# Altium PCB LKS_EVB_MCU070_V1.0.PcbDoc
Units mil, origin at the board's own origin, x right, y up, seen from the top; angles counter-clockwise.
Board outline 2625 x 1560 mil, 2 copper layers (Top Layer, Bottom Layer); 44 components, 81 nets, 209 pads, 64 vias.
Unrouted connection lines stored in the file: 4.
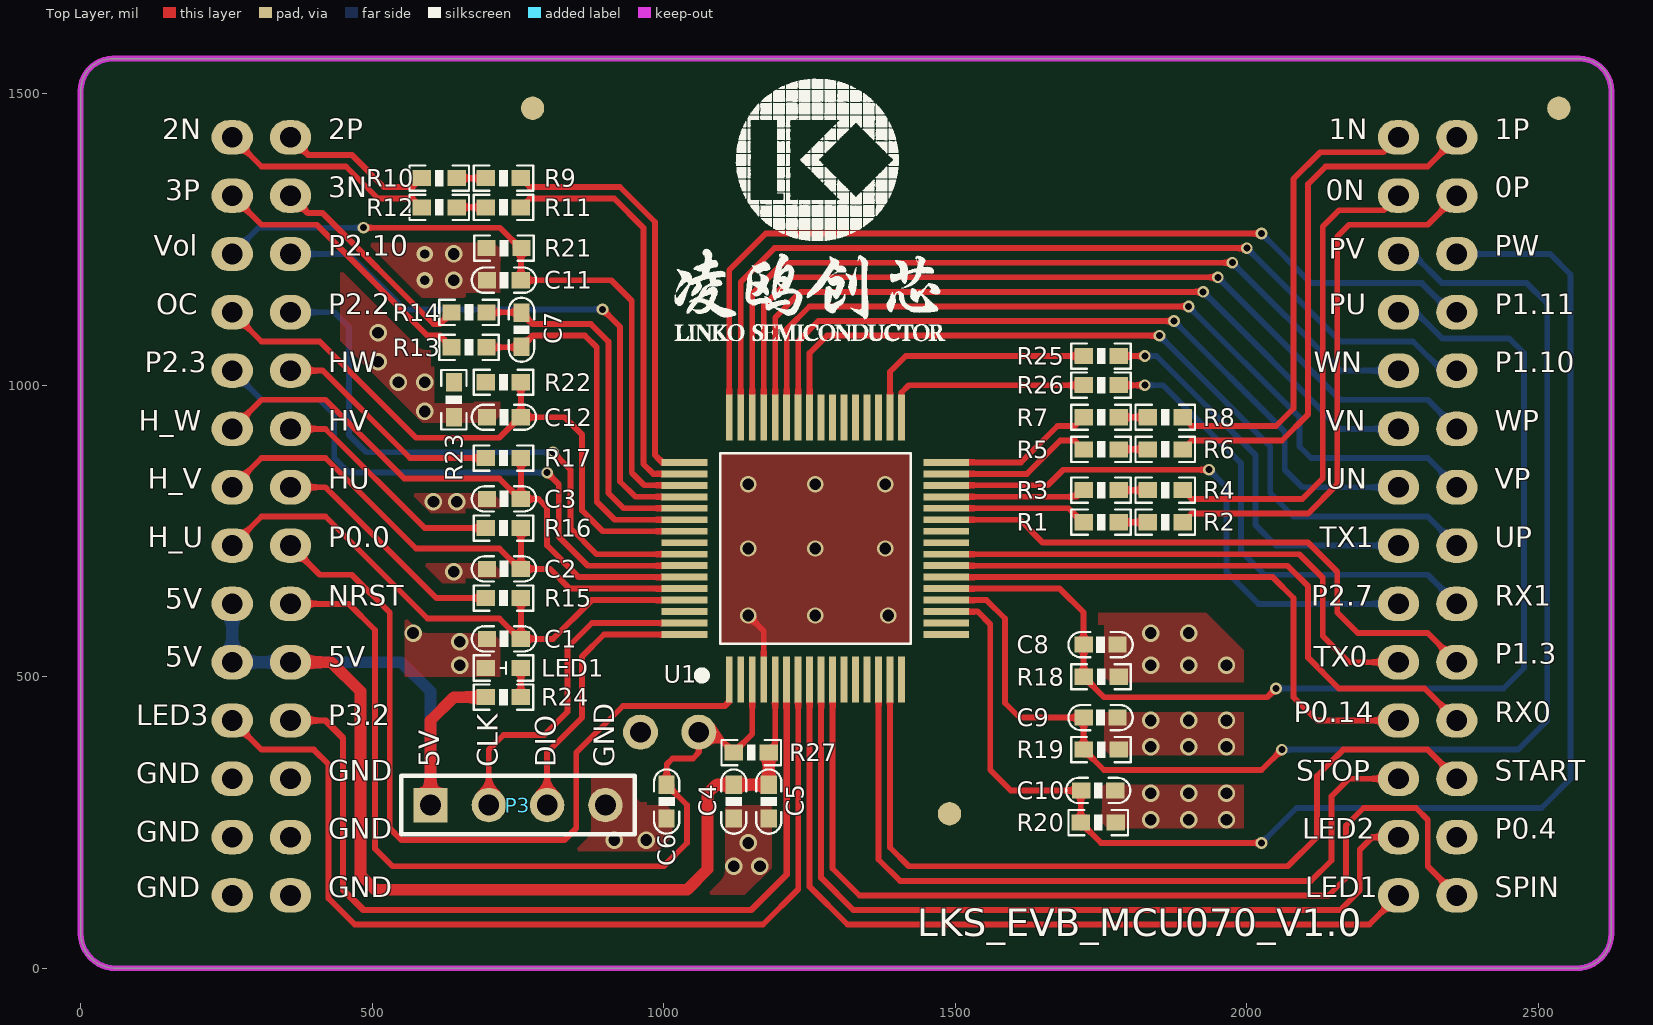
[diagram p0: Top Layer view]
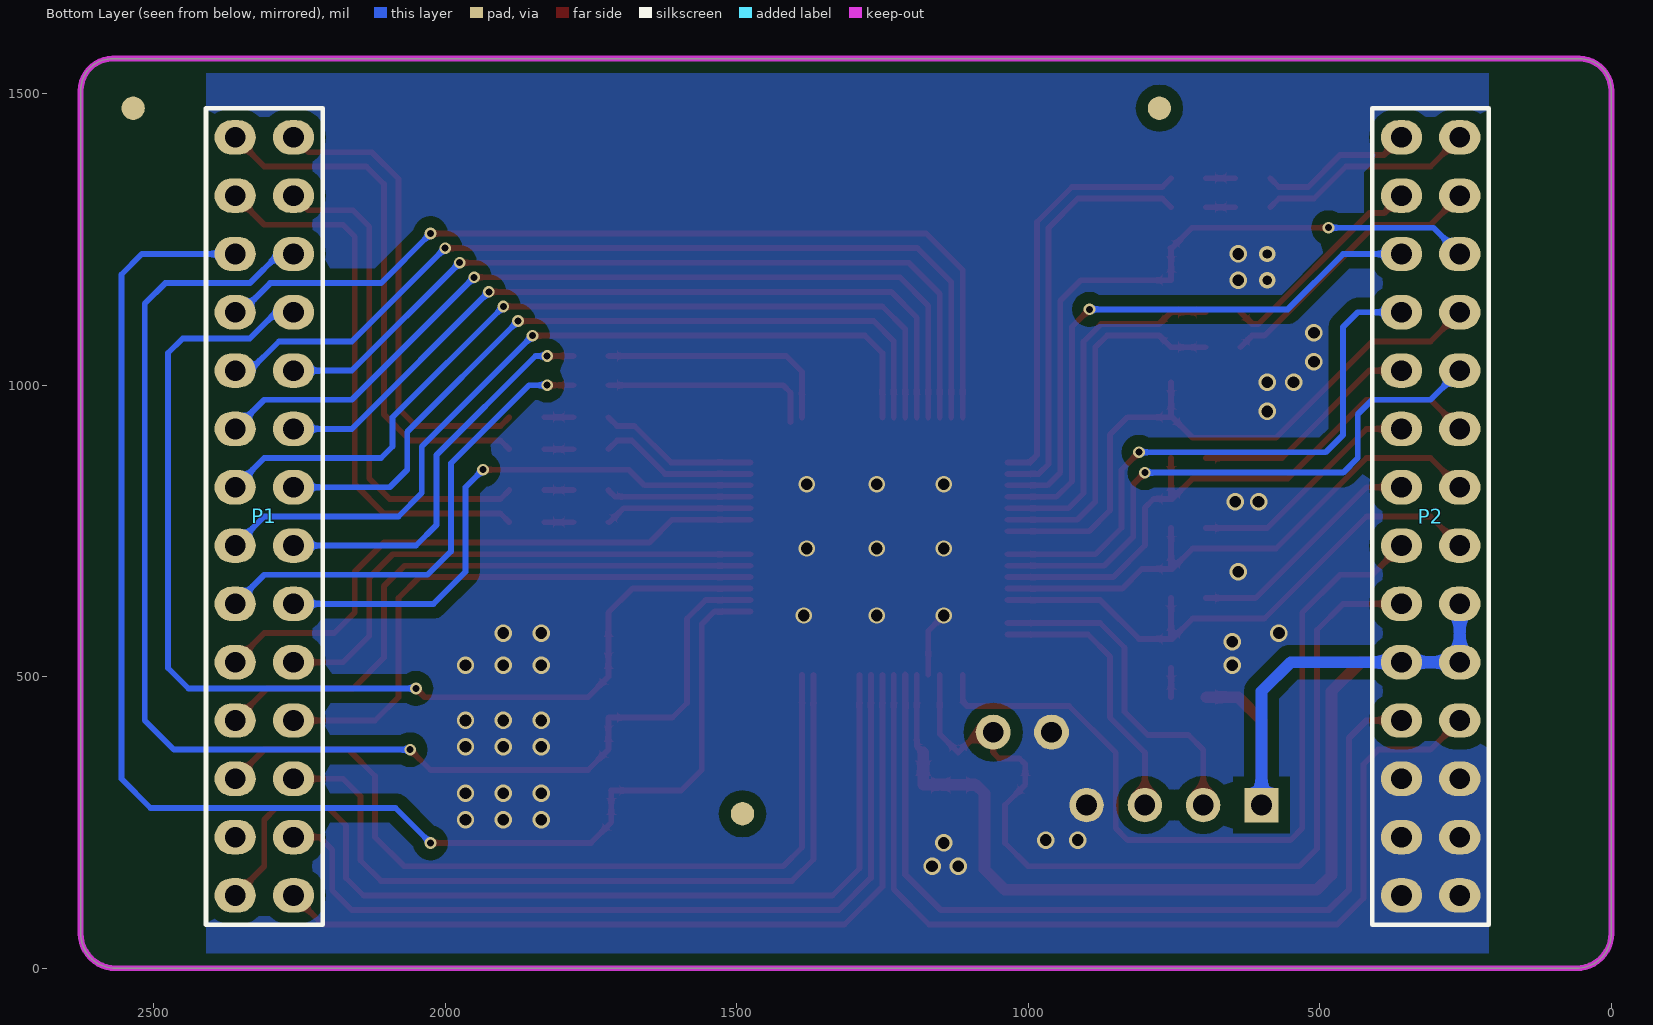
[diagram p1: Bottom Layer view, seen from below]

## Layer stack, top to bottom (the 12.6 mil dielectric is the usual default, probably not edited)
Top Solder: solder mask 0.4, Solder Resist, Dk 3.5
Top Layer: signal copper 1.4
Dielectric1: dielectric 12.6, FR-4, Dk 4.8
Bottom Layer: signal copper 1.4
Bottom Solder: solder mask 0.4, Solder Resist, Dk 3.5

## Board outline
0,60 0,1505 cw(c55,1505) 55,1560 2570,1560 cw(c2570,1505) 2625,1505 2625,60 cw(c2565,60) 2565,0 60,0 cw(c60,60)

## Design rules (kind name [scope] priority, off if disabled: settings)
Clearance Clearance_2 [InPolygon] p1: gap=20 ignorepadtopadclearanceinfootprint=FALSE except(0: Arc-Hole Track-Hole SMDPad-Hole THPad-Hole Via-Hole Fill-Hole Poly-Hole Region-Hole Text-Hole)
Clearance Clearance_1 [All] p2: gap=0 ignorepadtopadclearanceinfootprint=FALSE
ComponentClearance [All] p1: gap=0 collisioncheckmode=3 verticalgap=0 showdistances=FALSE
FabricationTestpoint [(IsPad And (OnTopLayer Or OnBottomLayer))] p1: side=3 testpointundercomponent=TRUE minsize=40 maxsize=100 preferedsize=60 minholesize=0 maxholesize=40 preferedholesize=32 testpointgrid=1 allowsidetop=TRUE allowsidebottom=TRUE usegrid=TRUE gridtolerance=0.01
HoleSize [All] p1: absolutevalues=TRUE maxlimit=100 minlimit=0 maxpercent=80.000 minpercent=20.000
PolygonConnect [All] p1: connectstyle=Direct reliefconductorwidth=10 reliefentries=4 polygonreliefangle="90 Angle" airgapwidth=10
RoutingVias [All] p1: holewidth=28 width=50 viastyle="Through Hole" minholewidth=0 minwidth=10 maxholewidth=28 maxwidth=50
SilkToSolderMaskClearance SilkscreenOverComponentPads [IsPad] p1: minsilkscreentomaskgap=10 clearancetoexposedcopper=TRUE
SolderMaskExpansion [All] p1: expansion=4 istentingtop=FALSE
Width [All] p1: maxlimit=100 minlimit=1 preferedwidth=10
26 further rules are at their usual default settings.

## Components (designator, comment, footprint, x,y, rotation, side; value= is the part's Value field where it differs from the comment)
C1 "10nF/16V" 0603C 726,565 r180 top
C2 "10nF/16V" 0603C 726,685 r180 top
C3 "10nF/16V" 0603C 726,805 r180 top
C4 "10uF/10V" 0603C 1120,285.95 r90 top
C5 "100nF/50V" 0603C 1180,285.95 r90 top
C6 "100nF/50V" 0603C 1005,286 r270 top
C7 "1nF/50V" 0603C 756,1095 r90 top
C8 "1nF/50V" 0603C 1749,555 r0 top
C9 "1nF/50V" 0603C 1749,430 r0 top
C10 "1nF/50V" 0603C 1745,305 r0 top
C11 "100nF/50V" 0603C 725.94,1180 r0 top
C12 "1nF/50V" 0603C 725.94,945 r0 top
LED1 "LED" "LED 0603R" 725,515 r180 top
P1 "Header 14X2A" "HDR 2X14 底层" 2260,1425 r180 bottom locked
P2 "Header 14X2A" "HDR 2X14 底层" 260,1425 r180 bottom locked
P3 "Header 4" HDR1X4 600,280 r0 top
R1 "20K1%" 0603R 1750,765 r180 top value=K
R2 "20K1%" 0603R 1860,765 r180 top value=K
R3 "20K1%" 0603R 1750,820 r180 top value=K
R4 "20K1%" 0603R 1860,820 r180 top value=K
R5 "20K1%" 0603R 1750,890 r180 top value=K
R6 "20K1%" 0603R 1860,890 r180 top value=K
R7 "20K1%" 0603R 1750,945 r180 top value=K
R8 "20K1%" 0603R 1860,945 r180 top value=K
R9 "20K1%" 0603R 725,1355 r0 top value=K
R10 "20K1%" 0603R 615,1355 r0 top value=K
R11 "20K1%" 0603R 725,1305 r0 top value=K
R12 "20K1%" 0603R 615,1305 r0 top value=K
R13 "1K1%" 0603R 666,1065 r0 top value=K
R14 "1K1%" 0603R 666,1125 r0 top value=K
R15 "2K" 0603R 725,635 r0 top value=K
R16 "2K" 0603R 725,755 r0 top value=K
R17 "2K" 0603R 725,875 r0 top value=K
R18 "1K" 0603R 1750,500 r0 top value=K
R19 "1K" 0603R 1750,375 r0 top value=K
R20 "1K" 0603R 1745,250 r0 top value=K
R21 "1K1%" 0603R 725.94,1235 r0 top value=K
R22 "1K1%" 0603R 725,1005 r180 top value=K
R23 "10R" 0603R 640,975 r270 top value=K
R24 "330R" 0603R 725,465 r0 top value=K
R25 "10R" 0603R 1750,1050 r0 top value=K
R26 "10R" 0603R 1750,1000 r0 top value=K
R27 "20K1%" 0603R 1150,370 r0 top value=K
U1 "LKS32MC070RBT8" LQFP64 1260,720 r0 top locked

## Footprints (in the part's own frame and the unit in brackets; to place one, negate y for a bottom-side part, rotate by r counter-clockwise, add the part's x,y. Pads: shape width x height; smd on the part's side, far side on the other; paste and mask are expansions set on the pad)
0603C [mm] "电容"
  rect 0.8x0.7 smd: 1(-0.737,0) 2(0.738,0)
  silkscreen extent -1.4,-0.55 1.4,0.55, body extent -0.8,-0.41 0.8,0.41, height 0.81
0603R [mm] "电阻"
  rect 0.8x0.7 smd: 1(-0.762,0) 2(0.762,0)
  silkscreen extent -1.3,-0.55 1.3,0.55, body extent -0.8,-0.4 0.8,0.4, height 0.45
HDR1X4 [mm] "Connector; Header; 4 Position"
  rect 1.5x1.5 hole 0.9: 1(0,0)
  round 1.5 hole 0.9: 2(2.54,0) 3(5.08,0) 4(7.62,0)
  silkscreen extent -1.27,-1.27 8.89,1.27
"HDR 2X14 底层" [mm] "双排针 2.54mm 底层"
  oval 1.8x1.5 hole 0.9: 1(0,0) 2(0,-2.54) 3(0,-5.08) 4(0,-7.62) 5(0,-10.16) 6(0,-12.7) 7(0,-15.24) 8(0,-17.78) 9(0,-20.32) 10(0,-22.86) 11(0,-25.4) 12(0,-27.94) 13(0,-30.48) 14(0,-33.02) 15(-2.54,0) 16(-2.54,-2.54) 17(-2.54,-5.08) 18(-2.54,-7.62) 19(-2.54,-10.16) 20(-2.54,-12.7) 21(-2.54,-15.24) 22(-2.54,-17.78) 23(-2.54,-20.32) 24(-2.54,-22.86) 25(-2.54,-25.4) 26(-2.54,-27.94) 27(-2.54,-30.48) 28(-2.54,-33.02)
  silkscreen extent -3.81,-34.29 1.27,1.27, body extent -3.81,-34.29 1.27,1.27, height 8.5
"LED 0603R" [mm] "LED"
  rect 0.8x0.7 smd: 1(-0.762,0) 2(0.762,0)
  silkscreen extent -1.3,-0.55 1.3,0.55, body extent -0.8,-0.4 0.8,0.4, height 0.47
LQFP64 [mm] "LINKO-080"
  rect 0.3x2 smd: 1(-3.75,-5.7) 2(-3.25,-5.7) 3(-2.75,-5.7) 4(-2.25,-5.7) 5(-1.75,-5.7) 6(-1.25,-5.7) 7(-0.75,-5.7) 8(-0.25,-5.7) 9(0.25,-5.7) 10(0.75,-5.7) 11(1.25,-5.7) 12(1.75,-5.7) 13(2.25,-5.7) 14(2.75,-5.7) 15(3.25,-5.7) 16(3.75,-5.7) 33(3.75,5.7) 34(3.25,5.7) 35(2.75,5.7) 36(2.25,5.7) 37(1.75,5.7) 38(1.25,5.7) 39(0.75,5.7) 40(0.25,5.7) 41(-0.25,5.7) 42(-0.75,5.7) 43(-1.25,5.7) 44(-1.75,5.7) 45(-2.25,5.7) 46(-2.75,5.7) 47(-3.25,5.7) 48(-3.75,5.7)
  rect 2x0.3 smd: 17(5.7,-3.75) 18(5.7,-3.25) 19(5.7,-2.75) 20(5.7,-2.25) 21(5.7,-1.75) 22(5.7,-1.25) 23(5.7,-0.75) 24(5.7,-0.25) 25(5.7,0.25) 26(5.7,0.75) 27(5.7,1.25) 28(5.7,1.75) 29(5.7,2.25) 30(5.7,2.75) 31(5.7,3.25) 32(5.7,3.75) 49(-5.7,3.75) 50(-5.7,3.25) 51(-5.7,2.75) 52(-5.7,2.25) 53(-5.7,1.75) 54(-5.7,1.25) 55(-5.7,0.75) 56(-5.7,0.25) 57(-5.7,-0.25) 58(-5.7,-0.75) 59(-5.7,-1.25) 60(-5.7,-1.75) 61(-5.7,-2.25) 62(-5.7,-2.75) 63(-5.7,-3.25) 64(-5.7,-3.75)
  silkscreen extent -5.12,-5.71 4.15,4.15, body extent -6,-6 6,6, height 1.05

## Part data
C1 C2 C3 C8 C9 C10: library part CAP, "Capacitor"
C4 C5 C6 C7 C11 C12: library part C, "Capacitor"
LED1: "LED_Light"
P1 P2: "Header, 14-Pin, Dual row"
P3: "Header, 4-Pin"
R1 R2 R3 R4 R5 R6 R7 R8 R9 R10 R11 R12 R13 R14 R15 R16 R17 R18 R19 R20 R21 R22 R23 R24 R25 R26 R27: library part Res, "Resistor"
U1: "芯片"

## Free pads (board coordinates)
  round 60 hole 35.43: 0(960,405) 1(1060,405)
  round 40 all layers, no hole: 0(2535,1475) 1(775,1475) 2(1490,265)

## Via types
v1: diameter 30, hole 20, Top Layer to Bottom Layer, 35 vias
v2: diameter 20, hole 12, Top Layer to Bottom Layer, 18 vias
v3: diameter 28, hole 20, Top Layer to Bottom Layer, 9 vias
v4: diameter 28, hole 16, Top Layer to Bottom Layer, 2 vias

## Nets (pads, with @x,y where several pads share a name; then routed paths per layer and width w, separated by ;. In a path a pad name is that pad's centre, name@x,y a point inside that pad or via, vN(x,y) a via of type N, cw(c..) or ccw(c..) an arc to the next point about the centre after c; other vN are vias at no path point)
+5V: C4.2 C5.2 P2.9 P2.10 P2.24 P3.1 R24.1 R27.2 U1.5 | length 2422.1
  Top Layer w10: R27.2 1191.1,381.1 U1.5@1191.1,503.46
  Top Layer w20: P2.24 430,525 480,475 480,160 505,135 1040,135 1075,170 1075,300 1090,315 C4.2 C5.2 R27.2 ; P3.1 600,425 640,465 R24.1
  Bottom Layer w20: P2.9 P2.10 P2.24 550,525 600,475 P3.1
CAN_RX: U1.11
CAN_TX: U1.12
GND: C1.2 C2.2 C3.2 C4.1 C5.1 C6.2 C8.2 C9.2 C10.2 C11.1 C12.1 LED1.2 P2.12 P2.13 P2.14 P2.16 P2.26 P2.27 P2.28 P3.4 pad.0@960,405 R14.1 R18.2 R19.2 R20.2 R21.1 R23.2 U1.4 | length 487.9
  Top Layer w10: P2.16 390,1295 415,1295 605,1105 616,1105 R14.1 ; v3(1145,605) 1171.42,578.58 U1.4@1171.42,503.46
  other v1: 1120,175 1165,175 1145,215 915,220 970,220 1835,255 1900,255 1965,255 1835,300 1900,300 1965,300 1835,380 1900,380 1965,380 1835,425 1900,425 1965,425 650,520 1835,520 1900,520 1965,520 650,560 570,575 1835,575 1900,575 640,680 605,800 645,800 590,955 545,1005 590,1005 510,1040 510,1090 640,1180 640,1225
  other v3: 1260,605 1385,605 1145,720 1260,720 1380,720 1145,830 1260,830 1380,830
  other v4: 590,1180 590,1225
HALL_U: C1.1 P2.8 R15.2 U1.61 | length 980.8
  Top Layer w10: P2.8 310,775 420,775 595,600 718.03,600 753.03,565 C1.1 ; R15.2 C1.1 ; U1.61 876.42,631.42 810,565 C1.1
HALL_V: C2.1 P2.7 R16.2 U1.60 | length 959
  Top Layer w10: P2.7 310,875 420,875 575,720 718.03,720 753.03,685 C2.1 ; R16.2 C2.1 ; U1.60 838.9,651.1 805,685 C2.1
HALL_W: C3.1 P2.6 R17.2 U1.59 | length 1030.4
  Top Layer w10: P2.6 310,975 420,975 555,840 718.03,840 753.03,805 C3.1 ; R17.2 C3.1 ; U1.59 854.21,670.79 800,725 800,790 785,805 C3.1
HU: P2.21 R15.1 | length 413.7
  Top Layer w10: P2.21 420,825 610,635 R15.1
HV: P2.20 R16.1 | length 405.4
  Top Layer w10: P2.20 420,925 590,755 R16.1
HW: P2.19 R17.1 | length 397.1
  Top Layer w10: P2.19 415,1025 565,875 R17.1
LED1: P1.14 U1.8 | length 1421
  Top Layer w10: U1.8@1250.16,503.46 1250.16,139.84 1315,75 2210,75 P1.14
LED2: P1.13 U1.9 | length 1454.1
  Top Layer w10: U1.9@1269.84,503.46 1269.84,155.16 1325,100 2160,100 2193.56,133.56 2193.56,203.56 2215,225 P1.13
LED3: P2.11 U1.7 | length 1643.2
  Top Layer w10: P2.11 310,375 400,375 425,350 425,120 470,75 1170,75 1230.47,135.47 U1.7@1230.47,503.46
NetLED1_1: LED1.1 R24.2 | length 50
  Top Layer w10: R24.2 LED1.1
NetR1_1: R1.1 R2.2 | length 50
  Top Layer w10: R1.1 R2.2
NetR3_1: R3.1 R4.2 | length 50
  Top Layer w10: R3.1 R4.2
NetR5_1: R5.1 R6.2 | length 50
  Top Layer w10: R5.1 R6.2
NetR7_1: R7.1 R8.2 | length 50
  Top Layer w10: R7.1 R8.2
NetR9_1: R9.1 R10.2 | length 50
  Top Layer w10: R10.2 R9.1
NetR11_1: R11.1 R12.2 | length 50
  Top Layer w10: R12.2 R11.1
NetR25_1: R25.1 U1.34 | length 421.8
  Top Layer w10: U1.34 1387.95,1022.95 1415,1050 R25.1
NetR26_1: R26.1 U1.33 | length 368.6
  Top Layer w10: U1.33@1407.64,936.54 1407.64,987.64 1420,1000 R26.1
NRST: C6.1 P2.23 pad.1@1060,405 R27.1 U1.3 | length 1571.5
  Top Layer w10: P2.23 460,625 505,580 505,205 535,175 1000,175 1040,215 1040,280 C6.1 1005,350 1015,360 1050,360 1060,370 1060,405 1085,405 R27.1 1151.73,401.73 U1.3@1151.73,503.46
OC: C12.2 P2.4 R22.1 U1.55 | length 1096.3
  Top Layer w10: P2.4 310,1075 410,1075 575,910 718.03,910 753.03,945 C12.2 ; R22.1 C12.2 ; U1.55 895.47,749.53 860,785 860,915 830,945 C12.2
OPA0_IN: R3.2 U1.29 | length 248.2
  Top Layer w10: U1.29@1476.54,808.58 1708.58,808.58 R3.2
OPA0_IP: R1.2 U1.28 | length 253.4
  Top Layer w10: U1.28@1476.54,788.9 1694.13,788.9 1718.03,765 R1.2
OPA1_IN: R7.2 U1.32 | length 275.5
  Top Layer w10: U1.32@1476.54,867.64 1612.64,867.64 1675,930 1705,930 R7.2
OPA1_IP: R5.2 U1.31 | length 273.3
  Top Layer w10: U1.31@1476.54,847.95 1622.95,847.95 1680,905 1705,905 R5.2
OPA2_IN: R11.2 U1.50 | length 719.6
  Top Layer w10: R11.2 770,1320 915,1320 965,1270 965,865 982.05,847.95 U1.50
OPA2_IP: R9.2 U1.49 | length 716.8
  Top Layer w10: R9.2 770,1340 925,1340 985,1280 985,880 997.36,867.64 U1.49
OPA3_IN: C7.2 R14.2 U1.53 | length 631.1
  Top Layer w10: R14.2 755.05,1125 C7.2 775.05,1105 875,1105 905,1075 905,815 931.1,788.9 U1.53
OPA3_IP: C7.1 R13.2 U1.54 | length 633.9
  Top Layer w10: R13.2 755,1065 C7.1 775,1085 865,1085 885,1065 885,800 915.79,769.21 U1.54
P0.0: P2.22 U1.1 | length 1398.9
  Top Layer w10: P2.22 410,675 465,675 530,610 530,240 550,220 830,220 850,240 850,370 930,450 1105,450 1112.36,457.36 U1.1@1112.36,503.46
P0.1: U1.2
P0.4: P1.27
P0.8: U1.16
P0.9: U1.17
P0.10: U1.18
P0.14: P1.11 U1.22 | length 984.9
  Top Layer w10: U1.22@1476.54,670.79 U1.22 2044.21,670.79 2080,635 2080,465 2120,425 P1.11
P1.1: U1.13
P1.2: U1.26
P1.3: P1.24 U1.27 | length 1025.6
  Top Layer w10: U1.27@1476.54,769.21 1610.79,769.21 1650,730 2105,730 2155,680 2155,610 2190,575 2310,575 P1.24
P1.10: P1.19 U1.47 | length 1571.6
  Top Layer w10: U1.47 1132.05,1177.05 1190,1235 v2(2000,1235)
  Bottom Layer w10: v2(2000,1235) 2160,1075 2285,1075 2335,1025 P1.19
P1.11: P1.18 U1.48 | length 1582.5
  Top Layer w10: U1.48 1112.36,1197.36 1175,1260 v2(2025,1260)
  Bottom Layer w10: v2(2025,1260) 2110,1175 2300,1175 2350,1125 P1.18
P1.12: U1.36
P1.13: U1.37
P1.14: U1.38
P1.15: U1.39
P2.0: U1.40
P2.2: P2.18 U1.57 | length 1014.4
  Top Layer w10: v2(810,885) 840,855 840,755 884.84,710.16 U1.57
  Bottom Layer w10: P2.18 435,1125 460,1100 460,915 490,885 v2(810,885)
P2.3: P2.5 U1.58 | length 1010.8
  Top Layer w10: v2(800,850) 820,830 820,740 869.53,690.47 U1.58
  Bottom Layer w10: P2.5 310,975 410,975 435,950 435,875 460,850 v2(800,850)
P2.7: P1.9 U1.30 | length 974.7
  Top Layer w10: U1.30@1476.54,828.27 1658.27,828.27 1685,855 v2(1935,855)
  Bottom Layer w10: v2(1935,855) 1965,825 1965,680 2020,625 P1.9
P2.10: P2.17 U1.52 | length 1003.3
  Top Layer w10: v2(895,1130) 925,1100 925,835 951.42,808.58 U1.52
  Bottom Layer w10: P2.17 460,1225 555,1130 v2(895,1130)
P2.13: U1.62
P3.2: P2.25 U1.6 | length 1505.6
  Top Layer w11: P2.25 420,425 450,395 450,135 485,100 1150,100 1210.79,160.79 U1.6@1210.79,503.46
P3.6: U1.25
P3.12: U1.56
P3.13: U1.35
PGND: P1.1 P1.2 P2.1 P2.2 R4.1 R8.1 R12.1 R13.1 R22.2 R23.1 | length 2515.1
  Top Layer w10: P2.2 310,1275 405,1275 595,1085 616,1085 R13.1 ; P2.1 310,1375 455,1375 510,1320 570,1320 R12.1 ; R4.1 1905,805 2095,805 2130,840 2130,1272.27 2157.73,1300 2235,1300 P1.2 ; R8.1 1905,930 2050,930 2080,960 2080,1353.77 2125.64,1399.41 2234.41,1399.41 P1.1
PU: C8.1 P1.4 R18.1 U1.21 | length 1944.7
  Top Layer w10: U1.21@1476.54,651.1 U1.21 1678.9,651.1 1720,610 C8.1 R18.1 1755,465 2035,465 v2(2050,480)
  Bottom Layer w10: v2(2050,480) 2440,480 2475,515 2475,1055 2450,1080 2335,1080 2290,1125 P1.4
PV: C9.1 P1.3 R19.1 U1.20 | length 2316.7
  Top Layer w10: U1.20@1476.54,631.42 1553.58,631.42 1585,600 1585,455 1610,430 C9.1 R19.1 1755,340 2025,340 v2(2060,375)
  Bottom Layer w10: v2(2060,375) 2465,375 2515,425 2515,1140 2480,1175 2335,1175 2285,1225 P1.3
PW: C10.1 P1.17 R20.1 U1.19 | length 2542.9
  Top Layer w10: U1.19@1476.54,611.73 1538.27,611.73 1560,590 1560,340 1595,305 C10.1 1715,304 R20.1 1750,215 v2(2025,215)
  Bottom Layer w10: v2(2025,215) 2085,275 2505,275 2555,325 2555,1190 2520,1225 P1.17
RXD0: P1.25 U1.23 | length 1065.2
  Top Layer w10: U1.23@1476.54,690.47 U1.23 2069.53,690.47 2105,655 2105,532.5 2157.5,480 2305,480 P1.25
RXD1: P1.23 R26.2 | length 823.8
  Top Layer w10: R26.2 v2(1825,1000)
  Bottom Layer w10: v2(1825,1000) 1856,1000 1990,866 1990,715 2030,675 2310,675 P1.23
SPIN: P1.28 U1.10 | length 1645.7
  Top Layer w10: U1.10@1289.53,503.46 1289.53,171.22 1335.75,125 2140,125 2170,155 2170,245 2200,275 2290,275 2310,255 2310,175 P1.28
START1: P1.26 U1.15 | length 1446.8
  Top Layer w10: U1.15@1387.95,503.46 1387.95,207.05 1420,175 2070,175 2120,225 2120,330 2165,375 2310,375 P1.26
STOP1: P1.12 U1.14 | length 1360.6
  Top Layer w10: U1.14@1368.27,503.46 1368.27,186.73 1405,150 2110,150 2145,185 2145,295 2175,325 P1.12
SWCLK: P3.2 U1.63 | length 584.9
  Top Layer w10: P3.2 700,375 725,400 795,400 835,440 835,550 877.05,592.05 U1.63
SWDIO: P3.3 U1.64 | length 470.9
  Top Layer w10: P3.3 800,370 860,430 860,535 897.36,572.36 U1.64
TXD0: P1.10 U1.24 | length 918.7
  Top Layer w10: U1.24@1476.54,710.16 U1.24 2089.84,710.16 2130,670 2130,570 2175,525 P1.10
TXD1: P1.8 R25.2 | length 684.9
  Top Layer w10: R25.2 v2(1825,1050)
  Bottom Layer w10: v2(1825,1050) 1845,1050 2015,880 2015,760 2050,725 P1.8
UN: P1.7 U1.42 | length 1331
  Top Layer w10: U1.42 1230.47,1075.47 1265,1110 v2(1875,1110)
  Bottom Layer w10: v2(1875,1110) 2065,920 2065,855 2095,825 P1.7
UP: P1.22 U1.41 | length 1428.9
  Top Layer w10: U1.41 1250.16,1055.16 1280,1085 v2(1850,1085)
  Bottom Layer w10: v2(1850,1085) 2040,895 2040,815 2080,775 2310,775 P1.22
UP-: P2.15 R10.1 | length 266.4
  Top Layer w10: P2.15 390,1395 465,1395 520,1340 570,1340 R10.1
VN: P1.6 U1.44 | length 1356.1
  Top Layer w10: U1.44 1191.1,1116.1 1235,1160 v2(1925,1160)
  Bottom Layer w10: v2(1925,1160) 2160,925 P1.6
VOL_ADC: C11.2 P2.3 R21.2 U1.51 | length 1183.6
  Top Layer w10: v2(485,1270) 718.98,1270 753.98,1235 R21.2 755,1234.06 C11.2 910,1180 945,1145 945,850 966.73,828.27 U1.51
  Bottom Layer w10: P2.3 305,1270 v2(485,1270)
VP: P1.21 U1.43 | length 1474.5
  Top Layer w10: U1.43 1210.79,1095.79 1250,1135 v2(1900,1135)
  Bottom Layer w10: v2(1900,1135) 2090,945 2090,895 2110,875 2310,875 P1.21
VP-: P1.15 R6.1 | length 923
  Top Layer w10: R6.1 1905,905 2060,905 2105,950 2105,1345 2135,1375 2310,1375 P1.15
WN: P1.5 U1.46 | length 1419.3
  Top Layer w10: U1.46 1151.73,1156.73 1205,1210 v2(1975,1210)
  Bottom Layer w10: v2(1975,1210) 2160,1025 P1.5
WP: P1.20 U1.45 | length 1508.4
  Top Layer w10: U1.45 1171.42,1136.42 1220,1185 v2(1950,1185)
  Bottom Layer w10: v2(1950,1185) 2160,975 2310,975 P1.20
WP-: P1.16 R2.1 | length 950.9
  Top Layer w10: R2.1 1905,780 2105,780 2155,830 2155,1255 2175,1275 2310,1275 P1.16

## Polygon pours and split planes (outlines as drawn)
GND on Top Layer "NONET_L-01_P-001" (solid, remove dead copper, pour order 16): 749.68,500 755,505.32 755,1270 475,1270 440,1235 445,1230 445,550 495,500
GND on Top Layer "NONET_L-01_P-001" (solid, remove dead copper, pour order 15): 850,330 850,175 1015,175 1090,100 1150,100 1210.79,160.79 1210,161.58 1210,285 960,285 950,295 950,330
GND on Top Layer "NONET_L-01_P-001" (solid, remove dead copper, pour order 13): 1720,610 1930,610 1994.74,545.26 1994.74,215 1750,215 1715,250
GND on Top Layer "NONET_L-01_P-001" (solid, remove dead copper, pour order 14): 1096.61,883.39 1423.39,883.39 1423.39,556.61 1096.61,556.61
GND on Bottom Layer "Bottom Layer-No Net 1" (solid, remove dead copper, pour order 12): 210,1560 210,0 2410,0 2410,1560

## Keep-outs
Keep-Out Layer:
  the board outline again, w10

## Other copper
Top Layer:
  pour cut-out: 310,1360 320,1370 320,1375 410,1375 420,1365 420,1314.94 454.94,1280 455,1280 585,1150 656.76,1150 666,1140.76 666,1101 660,1095 595,1095 415,1275 330,1275 310,1295
Bottom Layer:
  pour cut-out: 210,1380.02 409.98,1380.02 425,1365 425,1285 415,1275 210,1275

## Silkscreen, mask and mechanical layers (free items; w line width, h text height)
Top Overlay:
  drawing of 144 lines, arcs and shapes, not listed
  text "2N" at 140,1410 h60
  text "2P" at 425,1410 h60
  text "1N" at 2140,1410 h60
  text "1P" at 2425,1410 h60
  text "3N" at 424.94,1310 h60
  text "0P" at 2425,1310 h60
  text "3P" at 145,1305 h60
  text "0N" at 2135,1305 h60
  text "Vol" at 125,1210 h60
  text "P2.10" at 425,1210 h60
  text "PW" at 2425,1210 h60
  text "PV" at 2140,1205 h60
  text "OC" at 130,1110 h60
  text "P2.2" at 425,1110 h60
  text "PU" at 2140,1110 h60
  text "P1.11" at 2425,1110 h60
  text "P2.3" at 110,1010 h60
  text "HW" at 425,1010 h60
  text "WN" at 2115,1010 h60
  text "P1.10" at 2425,1010 h60
  text "H_W" at 100,910 h60
  text "HV" at 425,910 h60
  text "VN" at 2135,910 h60
  text "WP" at 2425,910 h60
  text "H_V" at 115,810 h60
  text "HU" at 425,810 h60
  text "UN" at 2135,810 h60
  text "VP" at 2425,810 h60
  text "H_U" at 115,710 h60
  text "P0.0" at 425,710 h60
  text "TX1" at 2125,710 h60
  text "UP" at 2425,710 h60
  text "NRST" at 425,610 h60
  text "P2.7" at 2110,610 h60
  text "RX1" at 2425,610 h60
  text "5V" at 145,605 h60
  text "P1.3" at 2425,510 h60
  text "5V" at 145,505 h60
  text "5V" at 425,505 h60
  text "TX0" at 2115,505 h60
  text "P0.14" at 2080,410 h60
  text "RX0" at 2425,410 h60
  text "LED3" at 95,405 h60
  text "P3.2" at 425,405 h60
  text "5V" at 615,345 h35 r90
  text "CLK" at 715,345 h35 r90
  text "DIO" at 815,345 h35 r90
  text "GND" at 915,345 h35 r90
  text "GND" at 425,310 h60
  text "STOP" at 2085,310 h60
  text "START" at 2425,310 h60
  text "GND" at 95,305 h60
  text "GND" at 425,210 h60
  text "LED2" at 2095,210 h60
  text "P0.4" at 2425,210 h60
  text "GND" at 95,205 h60
  text "GND" at 95,110 h60
  text "GND" at 425,110 h60
  text "LED1" at 2100,110 h60
  text "SPIN" at 2425,110 h60
  text "LKS_EVB_MCU070_V1.0" at 1435,40 h80
Top Solder:
  circle w78: c2535,1475 r17
  circle w78: c775,1475 r17
  circle w78: c1490,265 r17
Mechanical 1:
  the board outline again, w10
